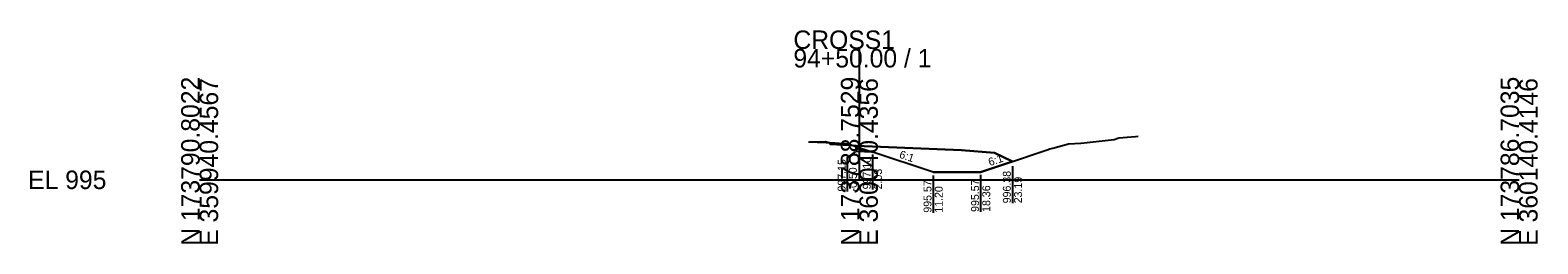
# Model space of a CAD drawing. Extents: x -26 to 1403, y -10 to 11027.
# Drawn here: x -25.7 to 202.8, y 9490.3 to 9522.7 of the extents above; entities that cross this region are included whole.
import ezdxf

# ---------------------------------------------------------------- set-up
doc = ezdxf.new("R2010")
doc.units = 0
for name, color, linetype in [('Default', 7, 'Continuous'), ('P_E_XS_Ground', 7, 'Continuous'), ('P_XS', 7, 'Continuous'), ('P_XS_EAR_CommonGrnd', 7, 'Continuous'), ('P_XS_Lane', 7, 'Continuous'), ('P_XS_Rock', 7, 'Continuous')]:
    doc.layers.add(name, color=color, linetype=linetype)

msp = doc.modelspace()

# ---------------------------------------------------------------- linework, layer by layer
at = {"layer": 'Default'}
for p, q in [((100, 9500), (100, 9519.81)), ((0, 9500), (100, 9500)), ((100, 9500), (200, 9500))]:
    msp.add_line(p, q, dxfattribs=at)
at = {"layer": 'P_E_XS_Ground'}
for p, q in [((92.45, 9505.77), (92.83, 9505.74)), ((92.83, 9505.74), (94.83, 9505.78)), ((94.83, 9505.78), (95.44, 9505.67)), ((95.44, 9505.67), (95.59, 9505.35)), ((99.5, 9505.14), (95.59, 9505.35)), ((115.5, 9504.5), (99.5, 9505.14)), ((128.47, 9504.53), (128.88, 9504.68)), ((128.88, 9504.68), (129.32, 9504.81)), ((129.32, 9504.81), (131.71, 9505.43)), ((131.71, 9505.43), (133.55, 9505.55)), ((133.55, 9505.55), (134.07, 9505.62)), ((134.07, 9505.62), (138.61, 9506.09)), ((138.61, 9506.09), (139.35, 9506.34)), ((139.35, 9506.34), (141.86, 9506.57)), ((141.86, 9506.57), (142.25, 9506.6)), ((120.5, 9504.1), (115.5, 9504.5)), ((123.19, 9502.76), (120.5, 9504.1)), ((123.19, 9502.76), (127.87, 9504.36)), ((127.87, 9504.36), (128.47, 9504.53))]:
    msp.add_line(p, q, dxfattribs=at)
at = {"layer": 'P_XS'}
for p, q in [((92.3, 9505.77), (96.3, 9505.61)), ((96.3, 9505.61), (98.3, 9505.45)), ((98.3, 9505.45), (102.03, 9504.2))]:
    msp.add_line(p, q, dxfattribs=at)
at = {"layer": 'P_XS_EAR_CommonGrnd'}
msp.add_lwpolyline([(99.5, 9504.31), (99.5, 9505.14), (115.5, 9504.5), (120.5, 9504.1), (123.19, 9502.76), (118.36, 9501.15), (111.2, 9501.15), (102.03, 9504.2)], close=True, dxfattribs=at)
at = {"layer": 'P_XS_Lane'}
for p, q in [((99.5, 9504.31), (99.5, 9505.14)), ((102.03, 9504.2), (99.5, 9504.31)), ((111.2, 9501.15), (102.03, 9504.2)), ((118.36, 9501.15), (123.19, 9502.76)), ((111.2, 9501.15), (118.36, 9501.15))]:
    msp.add_line(p, q, dxfattribs=at)
at = {"layer": 'P_XS_Rock'}
for p, q in [((98.16, 9503.35), (99.4, 9504.23)), ((98.16, 9503.35), (98.16, 9498.23)), ((101.97, 9503.78), (101.97, 9498.55)), ((111.18, 9500.63), (111.18, 9495.02)), ((118.38, 9500.76), (118.38, 9495.14)), ((123.2, 9502.06), (123.2, 9496.44))]:
    msp.add_line(p, q, dxfattribs=at)

# ---------------------------------------------------------------- texts
at = {"layer": 'Default'}
for s, p in [('CROSS1', (90, 9519.81)), ('94+50.00 / 1', (90, 9517.01)), ('EL 995', (-26, 9498.6))]:
    msp.add_text(s, height=2.8, dxfattribs=at).set_placement(p)
for s, p in [('N 173790.8022', (0, 9490)), ('E 359940.4567', (2.8, 9490)), ('N 173788.7529', (100, 9490)), ('E 360040.4356', (102.8, 9490)), ('N 173786.7035', (200, 9490)), ('E 360140.4146', (202.8, 9490))]:
    msp.add_text(s, height=2.8, rotation=90, dxfattribs=at).set_placement(p)
at = {"layer": 'P_XS_Rock'}
for s, rotation, p in [('997.15', 90, (97.91, 9498.23)), ('997.10', 90, (101.72, 9498.55)), ('6:1', 341.5651, (105.95, 9503.36)), ('6:1', 18.4349, (119.78, 9502.06)), ('-0.50', 90, (99.61, 9498.23)), ('2.03', 90, (103.42, 9498.55)), ('996.38', 90, (122.95, 9496.44)), ('23.19', 90, (124.65, 9496.44)), ('995.57', 90, (110.93, 9495.02)), ('11.20', 90, (112.63, 9495.02)), ('995.57', 90, (118.13, 9495.14)), ('18.36', 90, (119.83, 9495.14))]:
    msp.add_text(s, height=1.2, rotation=rotation, dxfattribs=at).set_placement(p)

doc.saveas('drawing.dxf')
